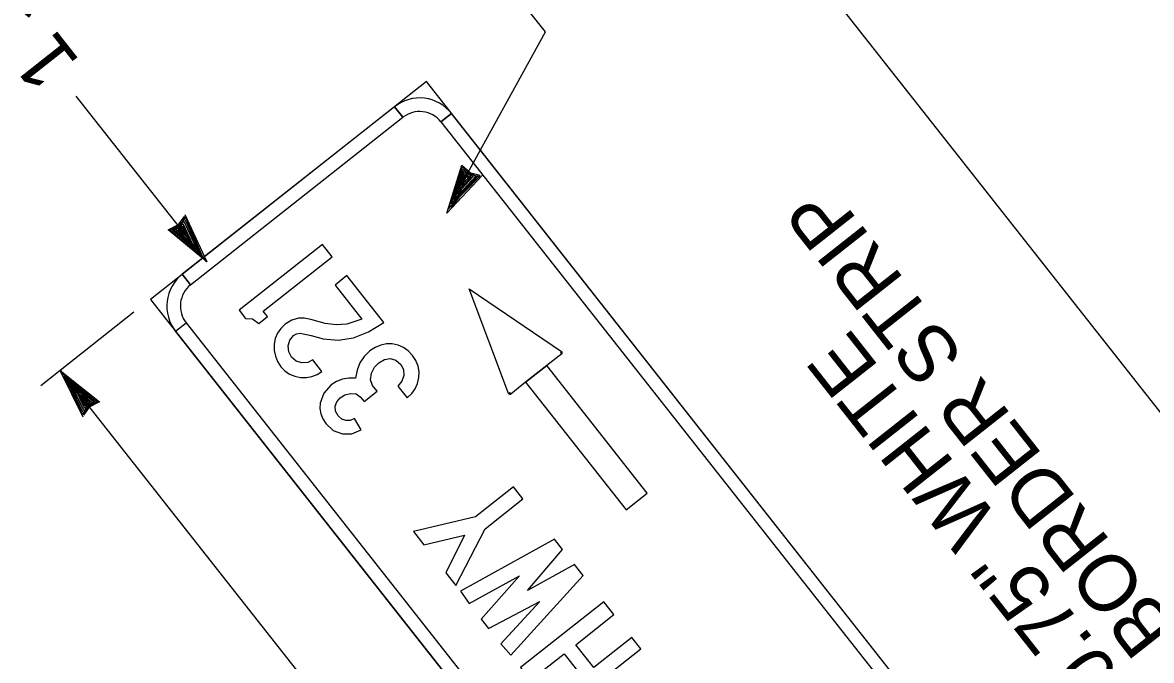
# Model space of a CAD drawing. Extents: x 671946 to 673995, y 1673066 to 1674936.
# Drawn here: x 672680.8 to 672764.3, y 1673663.1 to 1673710.3 of the extents above; entities that cross this region are included whole.
import ezdxf

# ---------------------------------------------------------------- set-up
doc = ezdxf.new("R2010")
doc.units = 0
doc.layers.add('C-ANNO-SYMB', color=7, linetype='Continuous')
doc.layers.add('Level 1', color=7, linetype='Continuous')

msp = doc.modelspace()

# ---------------------------------------------------------------- linework, layer by layer
at = {"layer": 'C-ANNO-SYMB'}
for p, q in [((672710.703, 1673705.901), (672690.285, 1673689.804)), ((672762.708, 1673639.935), (672710.703, 1673705.901)), ((672708.348, 1673704.044), (672692.641, 1673691.662)), ((672693.26, 1673690.876), (672708.967, 1673703.259)), ((672708.348, 1673704.044), (672708.967, 1673703.259)), ((672708.967, 1673703.259), (672708.348, 1673704.044)), ((672708.967, 1673703.259), (672708.348, 1673704.044)), ((672708.967, 1673703.259), (672708.967, 1673703.259)), ((672708.967, 1673703.259), (672708.967, 1673703.259)), ((672711.775, 1673702.926), (672712.561, 1673703.545)), ((672712.561, 1673703.545), (672711.775, 1673702.926)), ((672760.851, 1673642.291), (672712.561, 1673703.545)), ((672711.775, 1673702.926), (672760.065, 1673641.672)), ((672693.26, 1673690.876), (672692.641, 1673691.662)), ((672692.641, 1673691.662), (672693.26, 1673690.876)), ((672713.874, 1673690.573), (672713.874, 1673690.573)), ((672713.874, 1673690.573), (672713.874, 1673690.573)), ((672716.787, 1673682.847), (672713.874, 1673690.573)), ((672713.874, 1673690.573), (672720.707, 1673685.937)), ((672690.285, 1673689.804), (672742.29, 1673623.838)), ((672692.143, 1673687.449), (672692.928, 1673688.068)), ((672692.143, 1673687.449), (672692.928, 1673688.068)), ((672740.433, 1673626.194), (672692.143, 1673687.449)), ((672692.928, 1673688.068), (672692.928, 1673688.068)), ((672692.928, 1673688.068), (672692.928, 1673688.068)), ((672692.928, 1673688.068), (672741.218, 1673626.813)), ((672720.711, 1673685.776), (672719.612, 1673684.91)), ((672720.707, 1673685.937), (672720.649, 1673685.855)), ((672720.649, 1673685.855), (672720.707, 1673685.937)), ((672720.649, 1673685.855), (672720.711, 1673685.776)), ((672720.711, 1673685.776), (672720.649, 1673685.855)), ((672718.041, 1673683.671), (672719.612, 1673684.91)), ((672718.041, 1673683.671), (672719.612, 1673684.91)), ((672719.612, 1673684.91), (672718.041, 1673683.671)), ((672727.041, 1673675.486), (672719.612, 1673684.91)), ((672718.041, 1673683.671), (672716.942, 1673682.805)), ((672718.041, 1673683.671), (672725.47, 1673674.248)), ((672716.88, 1673682.883), (672716.787, 1673682.847)), ((672716.787, 1673682.847), (672716.88, 1673682.883)), ((672716.942, 1673682.805), (672716.88, 1673682.883)), ((672716.88, 1673682.883), (672716.942, 1673682.805)), ((672725.47, 1673674.248), (672727.041, 1673675.486)), ((672727.041, 1673675.486), (672727.041, 1673675.486)), ((672727.041, 1673675.486), (672727.041, 1673675.486))]:
    msp.add_line(p, q, dxfattribs=at)
for points in [[(672703.721, 1673692.952), (672703.011, 1673693.852), (672696.85, 1673688.995), (672697.32, 1673688.399), (672697.843, 1673688.358), (672698.294, 1673688.019), (672698.939, 1673688.528), (672698.621, 1673688.931)], [(672703.941, 1673690.861), (672705.92, 1673688.351), (672704.816, 1673687.973), (672704.018, 1673687.913), (672703.211, 1673688.017), (672702.162, 1673688.314), (672701.667, 1673688.414), (672701.242, 1673688.418), (672700.746, 1673688.274), (672700.247, 1673687.967), (672699.926, 1673687.659), (672699.683, 1673687.309), (672699.522, 1673686.915), (672699.439, 1673686.479), (672699.443, 1673686.032), (672699.526, 1673685.608), (672699.694, 1673685.205), (672699.941, 1673684.825), (672700.24, 1673684.512), (672700.58, 1673684.275), (672700.964, 1673684.115), (672701.385, 1673684.034), (672701.821, 1673684.029), (672702.23, 1673684.1), (672702.618, 1673684.25), (672702.977, 1673684.478), (672702.31, 1673685.323), (672701.927, 1673685.126), (672701.488, 1673685.1), (672701.068, 1673685.242), (672700.73, 1673685.537), (672700.531, 1673685.923), (672700.486, 1673686.371), (672700.598, 1673686.799), (672700.863, 1673687.12), (672701.098, 1673687.257), (672701.355, 1673687.316), (672702.184, 1673687.144), (672703.074, 1673686.886), (672704.186, 1673686.799), (672705.303, 1673686.97), (672706.427, 1673687.4), (672707.556, 1673688.088), (672704.822, 1673691.555)], [(672709.278, 1673682.519), (672709.618, 1673682.841), (672709.873, 1673683.201), (672710.05, 1673683.593), (672710.145, 1673684.019), (672710.161, 1673684.454), (672710.084, 1673684.874), (672709.92, 1673685.275), (672709.663, 1673685.663), (672709.349, 1673685.999), (672708.995, 1673686.252), (672708.607, 1673686.422), (672708.178, 1673686.507), (672707.744, 1673686.506), (672707.323, 1673686.419), (672706.917, 1673686.246), (672706.526, 1673685.99), (672706.101, 1673685.581), (672705.782, 1673685.109), (672705.572, 1673684.576), (672705.467, 1673683.986), (672704.961, 1673683.988), (672704.49, 1673683.905), (672704.058, 1673683.736), (672703.66, 1673683.479), (672703.11, 1673682.872), (672702.842, 1673682.141), (672702.822, 1673681.731), (672702.883, 1673681.342), (672703.03, 1673680.97), (672703.26, 1673680.615), (672703.814, 1673680.115), (672704.482, 1673679.867), (672705.195, 1673679.874), (672705.878, 1673680.15), (672705.371, 1673681.005), (672705.066, 1673680.857), (672704.746, 1673680.84), (672704.439, 1673680.953), (672704.172, 1673681.199), (672703.987, 1673681.542), (672703.951, 1673681.903), (672704.065, 1673682.24), (672704.315, 1673682.523), (672704.678, 1673682.74), (672705.078, 1673682.849), (672705.509, 1673682.815), (672705.813, 1673682.596), (672706.091, 1673682.243), (672707.058, 1673683.005), (672706.715, 1673683.439), (672706.556, 1673683.843), (672706.634, 1673684.343), (672706.855, 1673684.781), (672707.174, 1673685.121), (672707.597, 1673685.365), (672708.02, 1673685.435), (672708.452, 1673685.317), (672708.818, 1673684.996), (672709.017, 1673684.608), (672709.031, 1673684.176), (672708.883, 1673683.753), (672708.587, 1673683.394)], [(672710.508, 1673671.67), (672713.508, 1673672.373), (672712.141, 1673669.599), (672712.885, 1673668.655), (672715.045, 1673672.847), (672717.837, 1673675.047), (672717.136, 1673675.936), (672714.344, 1673673.735), (672709.75, 1673672.633)], [(672722.3, 1673669.386), (672721.651, 1673670.209), (672718.181, 1673668.294), (672720.776, 1673671.319), (672720.176, 1673672.08), (672713.224, 1673668.225), (672713.858, 1673667.317), (672717.601, 1673669.379), (672714.76, 1673666.173), (672715.308, 1673665.478), (672719.104, 1673667.473), (672716.205, 1673664.34), (672716.946, 1673663.504)], [(672726.575, 1673663.963), (672725.908, 1673664.808), (672723.081, 1673662.579), (672721.747, 1673664.271), (672724.575, 1673666.5), (672723.832, 1673667.442), (672717.671, 1673662.585), (672718.413, 1673661.643), (672720.884, 1673663.591), (672722.218, 1673661.899), (672719.747, 1673659.951), (672720.413, 1673659.106)]]:
    msp.add_lwpolyline(points, close=True, dxfattribs=at)
for centre, radius, start, end in [((672710.205, 1673701.688), 3, 38.2506, 128.25081), ((672710.205, 1673701.688), 2, 38.2506, 128.25081), ((672694.499, 1673689.306), 3, 128.25054, 218.25075), ((672694.499, 1673689.306), 2, 128.25054, 218.25075), ((672720.649, 1673685.855), 0.1, 308.25039, 55.35339), ((672716.88, 1673682.883), 0.1, 201.14796, 308.25039)]:
    msp.add_arc(centre, radius, start, end, dxfattribs=at)
at = {"layer": 'Level 1'}
for p, q in [((672685.683, 1673782.024), (672825.472, 1673604.707)), ((672694.452, 1673692.57), (672684.794, 1673704.821)), ((672712.207, 1673696.184), (672713.324, 1673699.734)), ((672712.325, 1673696.483), (672713.361, 1673699.589)), ((672712.554, 1673696.866), (672713.419, 1673699.431)), ((672712.722, 1673697.039), (672713.554, 1673699.199)), ((672712.744, 1673697.18), (672713.468, 1673699.309)), ((672713.324, 1673699.734), (672713.964, 1673699.167)), ((672713.361, 1673699.589), (672713.882, 1673699.185)), ((672713.605, 1673699.077), (672713.406, 1673698.188)), ((672713.419, 1673699.431), (672713.641, 1673699.238)), ((672713.468, 1673699.309), (672714.354, 1673698.903)), ((672713.554, 1673699.199), (672714.166, 1673698.893)), ((672714.053, 1673698.96), (672713.605, 1673699.077)), ((672713.641, 1673699.238), (672714.354, 1673698.903)), ((672713.882, 1673699.185), (672714.678, 1673698.985)), ((672713.964, 1673699.167), (672714.301, 1673698.965)), ((672714.862, 1673698.984), (672712.207, 1673696.184)), ((672714.493, 1673698.879), (672712.353, 1673696.528)), ((672714.662, 1673698.903), (672712.47, 1673696.671)), ((672714.354, 1673698.903), (672712.722, 1673697.039)), ((672714.354, 1673698.903), (672712.744, 1673697.18)), ((672713.027, 1673697.652), (672713.555, 1673699.044)), ((672714.166, 1673698.893), (672713.027, 1673697.652)), ((672713.291, 1673698.043), (672713.567, 1673698.913)), ((672714, 1673698.871), (672713.291, 1673698.043)), ((672713.882, 1673698.879), (672713.497, 1673698.44)), ((672713.497, 1673698.44), (672713.623, 1673698.852)), ((672713.555, 1673699.044), (672714, 1673698.871)), ((672713.567, 1673698.913), (672713.882, 1673698.879)), ((672713.623, 1673698.852), (672713.723, 1673698.821)), ((672713.723, 1673698.821), (672714.053, 1673698.96)), ((672714.301, 1673698.965), (672714.662, 1673698.903)), ((672714.451, 1673698.965), (672714.493, 1673698.879)), ((672713.206, 1673698.003), (672712.994, 1673697.548)), ((672712.994, 1673697.548), (672713.325, 1673697.899)), ((672713.406, 1673698.188), (672713.206, 1673698.003)), ((672712.536, 1673696.63), (672713.129, 1673697.314)), ((672713.129, 1673697.314), (672712.554, 1673696.866)), ((672692.313, 1673695.259), (672692.8, 1673695.92)), ((672692.675, 1673695.563), (672692.869, 1673695.873)), ((672692.8, 1673695.92), (672692.732, 1673695.702)), ((672692.821, 1673696.066), (672694.452, 1673692.57)), ((672692.869, 1673695.873), (672694.101, 1673692.998)), ((672691.592, 1673694.951), (672692.36, 1673695.328)), ((672694.452, 1673692.57), (672691.592, 1673694.951)), ((672691.74, 1673694.93), (672692.313, 1673695.259)), ((672694.221, 1673692.793), (672691.74, 1673694.93)), ((672691.909, 1673694.924), (672692.172, 1673695.056)), ((672693.953, 1673693.15), (672691.909, 1673694.924)), ((672692.04, 1673694.923), (672692.753, 1673695.589)), ((672693.735, 1673693.445), (672692.04, 1673694.923)), ((672692.172, 1673695.056), (672692.753, 1673695.589)), ((672692.175, 1673694.961), (672692.69, 1673695.411)), ((672693.857, 1673693.371), (672692.175, 1673694.961)), ((672692.585, 1673695.331), (672692.306, 1673694.961)), ((672692.306, 1673694.961), (672693.054, 1673694.44)), ((672692.318, 1673694.903), (672692.647, 1673695.249)), ((672693.405, 1673693.886), (672692.318, 1673694.903)), ((672692.36, 1673695.328), (672692.675, 1673695.563)), ((672692.444, 1673694.865), (672692.596, 1673695.143)), ((672692.522, 1673694.893), (672692.589, 1673694.974)), ((672692.856, 1673694.62), (672692.522, 1673694.893)), ((672692.589, 1673694.974), (672692.585, 1673695.331)), ((672692.596, 1673695.143), (672692.856, 1673694.62)), ((672692.647, 1673695.249), (672693.144, 1673694.278)), ((672692.69, 1673695.411), (672693.405, 1673693.886)), ((672692.732, 1673695.702), (672692.827, 1673695.708)), ((672692.753, 1673695.589), (672693.735, 1673693.445)), ((672692.753, 1673695.589), (672693.857, 1673693.371)), ((672692.827, 1673695.708), (672694.19, 1673692.835)), ((672693.144, 1673694.278), (672692.444, 1673694.865)), ((672693.054, 1673694.44), (672693.149, 1673694.184)), ((672689.068, 1673688.855), (672682.164, 1673683.412)), ((672685.312, 1673681.089), (672683.608, 1673684.55)), ((672683.608, 1673684.55), (672686.517, 1673682.229)), ((672704.456, 1673658.174), (672683.642, 1673684.577)), ((672683.968, 1673684.13), (672683.844, 1673684.333)), ((672683.844, 1673684.333), (672686.368, 1673682.247)), ((672685.298, 1673681.447), (672683.876, 1673684.291)), ((672683.876, 1673684.291), (672683.905, 1673684.083)), ((672683.905, 1673684.083), (672684.33, 1673683.284)), ((672685.259, 1673681.281), (672683.968, 1673684.13)), ((672684.33, 1673683.284), (672684.12, 1673683.981)), ((672684.12, 1673683.981), (672686.2, 1673682.25)), ((672685.37, 1673681.568), (672684.219, 1673683.763)), ((672684.219, 1673683.763), (672685.934, 1673682.207)), ((672685.37, 1673681.568), (672684.343, 1673683.691)), ((672684.343, 1673683.691), (672686.068, 1673682.248)), ((672684.944, 1673682.963), (672684.597, 1673683.325)), ((672684.597, 1673683.325), (672684.804, 1673682.889)), ((672685.428, 1673681.747), (672684.682, 1673683.257)), ((672684.682, 1673683.257), (672685.79, 1673682.263)), ((672685.045, 1673682.71), (672684.944, 1673682.963)), ((672685.468, 1673681.909), (672684.951, 1673682.87)), ((672684.951, 1673682.87), (672685.663, 1673682.298)), ((672685.803, 1673682.204), (672685.045, 1673682.71)), ((672685.517, 1673682.017), (672685.247, 1673682.534)), ((672685.247, 1673682.534), (672685.586, 1673682.268)), ((672685.447, 1673681.595), (672685.259, 1673681.281)), ((672685.803, 1673681.906), (672685.33, 1673681.236)), ((672686.068, 1673682.248), (672685.37, 1673681.568)), ((672685.94, 1673682.112), (672685.37, 1673681.568)), ((672685.934, 1673682.207), (672685.428, 1673681.747)), ((672685.757, 1673681.837), (672685.447, 1673681.595)), ((672685.79, 1673682.263), (672685.468, 1673681.909)), ((672685.663, 1673682.298), (672685.517, 1673682.017)), ((672685.586, 1673682.268), (672685.521, 1673682.186)), ((672685.521, 1673682.186), (672685.532, 1673681.828)), ((672685.532, 1673681.828), (672685.803, 1673682.204)), ((672686.517, 1673682.229), (672685.757, 1673681.837)), ((672686.368, 1673682.247), (672685.803, 1673681.906)), ((672686.2, 1673682.25), (672685.94, 1673682.112)), ((672685.393, 1673681.455), (672685.298, 1673681.447))]:
    msp.add_line(p, q, dxfattribs=at)
msp.add_lwpolyline([(672713.345, 1673698.392), (672719.507, 1673709.568), (672716.761, 1673713.051)], dxfattribs=at)

# ---------------------------------------------------------------- texts
for s, p in [('1 SIGN REQUIRED', (672685.151, 1673707.36)), ('BORDER STRIP', (672766.422, 1673665.494)), ('0.75" WHITE ', (672762.128, 1673662.109))]:
    msp.add_text(s, height=4.2, rotation=128.25054, dxfattribs=at).set_placement(p)

doc.saveas('drawing.dxf')
